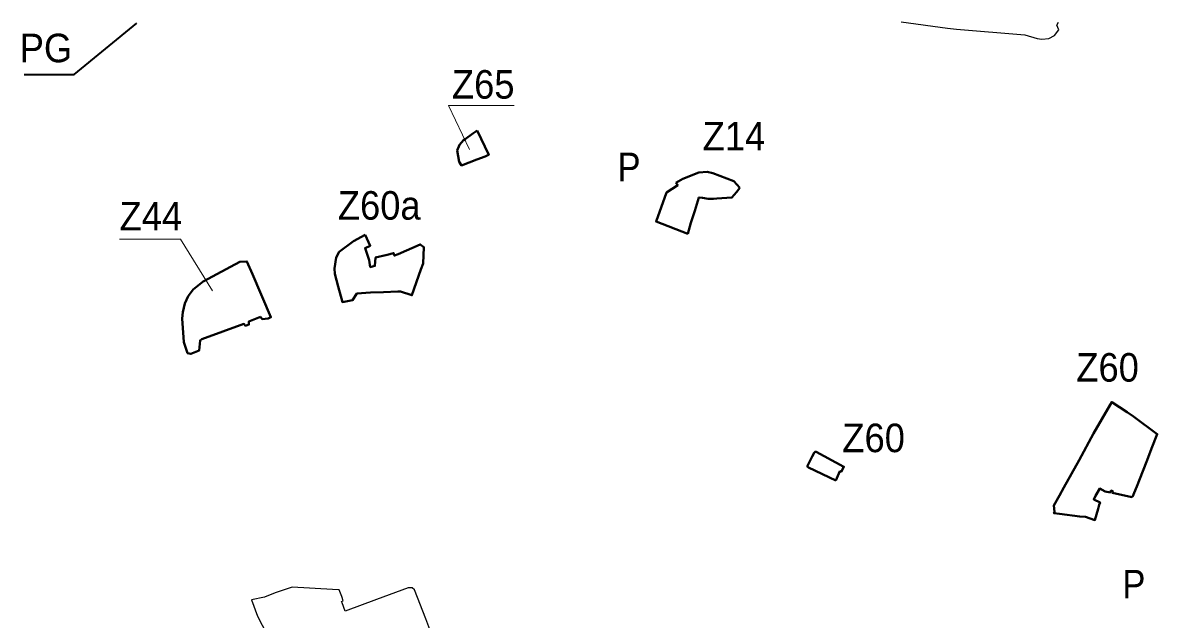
# Model space of a CAD drawing. Extents: x -650276 to -642489, y -1074311 to -1066658.
# Drawn here: x -647715 to -646763, y -1070697 to -1070195 of the extents above; entities that cross this region are included whole.
import ezdxf

# ---------------------------------------------------------------- set-up
doc = ezdxf.new("R2010")
doc.units = 0
doc.header["$LTSCALE"] = 9.6
for name, color, linetype, lineweight in [('42', 7, 'Continuous', 25), ('45', 7, 'Continuous', 40), ('46', 7, 'Continuous', 13), ('60', 7, 'Continuous', 35)]:
    doc.layers.add(name, color=color, linetype=linetype, lineweight=lineweight)

msp = doc.modelspace()

# ---------------------------------------------------------------- linework, layer by layer
at = {"layer": '42'}
for points in [[(-646977.7, -1070194.45), (-646938.98, -1070199.89), (-646931.25, -1070200.56), (-646874.04, -1070205.5), (-646863.66, -1070208.37), (-646859.54, -1070209.09), (-646853.67, -1070208.44), (-646849.15, -1070205.9), (-646845.3, -1070201.3), (-646847.17, -1070197.38), (-646845.76, -1070194.67)], [(-647367.67, -1070720.73), (-647377.04, -1070696.22), (-647386.39, -1070671.74), (-647388.31, -1070669.95), (-647391.74, -1070670.16), (-647418.28, -1070679.89), (-647444.78, -1070689.6), (-647447.31, -1070682.72), (-647447.76, -1070681.5), (-647446.22, -1070680.91), (-647447.58, -1070677.36), (-647449.69, -1070671.81), (-647455.17, -1070671.48), (-647489.21, -1070669.41), (-647496.64, -1070671.93), (-647503.3, -1070674.3), (-647512.51, -1070677.98), (-647523.27, -1070680.11), (-647518.19, -1070693.93), (-647502.59, -1070724.13)]]:
    msp.add_lwpolyline(points, dxfattribs=at)
at = {"layer": '45'}
for points in [[(-647333.87, -1070285.66), (-647324.11, -1070306.21), (-647324.94, -1070306.63), (-647327.18, -1070307.52), (-647333.97, -1070310.22), (-647346.97, -1070315.05), (-647349, -1070312), (-647350.67, -1070302.55), (-647348.677, -1070297.894), (-647345.27, -1070293.99), (-647343.9, -1070292.96), (-647337.56, -1070288.43), (-647334.91, -1070286.51)], [(-647333.87, -1070285.66), (-647324.11, -1070306.21), (-647324.94, -1070306.63), (-647327.18, -1070307.52), (-647333.97, -1070310.22), (-647346.97, -1070315.05), (-647349, -1070312), (-647350.67, -1070302.55), (-647348.677, -1070297.894), (-647345.27, -1070293.99), (-647343.9, -1070292.96), (-647337.56, -1070288.43), (-647334.91, -1070286.51)], [(-647427.8, -1070373.32), (-647437.76, -1070378.66), (-647449.69, -1070387.83), (-647452.17, -1070392.38), (-647453.71, -1070401.81), (-647453.35, -1070406.09), (-647450.51, -1070416.96), (-647446.93, -1070429.99), (-647438.45, -1070428.47), (-647434.85, -1070422.64), (-647423.38, -1070421.87), (-647412.51, -1070421.5), (-647400.41, -1070421.08), (-647398.21, -1070421.15), (-647388.6, -1070424.24), (-647381.11, -1070402.45), (-647379.3, -1070397.57), (-647378.49, -1070383.91), (-647381.65, -1070381.45), (-647400.22, -1070389.64), (-647403.27, -1070390.91), (-647404, -1070388.84), (-647409.36, -1070390.24), (-647419.08, -1070392.52), (-647419.68, -1070399.59), (-647423.58, -1070400.59), (-647424.54, -1070394.78), (-647425.99, -1070390.47), (-647427.96, -1070384.64), (-647423.57, -1070382.64)], [(-647427.8, -1070373.32), (-647437.76, -1070378.66), (-647449.69, -1070387.83), (-647452.17, -1070392.38), (-647453.71, -1070401.81), (-647453.35, -1070406.09), (-647450.51, -1070416.96), (-647446.93, -1070429.99), (-647438.45, -1070428.47), (-647434.85, -1070422.64), (-647423.38, -1070421.87), (-647412.51, -1070421.5), (-647400.41, -1070421.08), (-647398.21, -1070421.15), (-647388.6, -1070424.24), (-647381.11, -1070402.45), (-647379.3, -1070397.57), (-647378.49, -1070383.91), (-647381.65, -1070381.45), (-647400.22, -1070389.64), (-647403.27, -1070390.91), (-647404, -1070388.84), (-647409.36, -1070390.24), (-647419.08, -1070392.52), (-647419.68, -1070399.59), (-647423.58, -1070400.59), (-647424.54, -1070394.78), (-647425.99, -1070390.47), (-647427.96, -1070384.64), (-647423.57, -1070382.64)], [(-647515.73, -1070442.32), (-647514.23, -1070444.18), (-647509.22, -1070443.62), (-647506.95, -1070442.71), (-647522.54, -1070406.51), (-647527.1, -1070395.72), (-647533.1, -1070396.26), (-647564.01, -1070412.59), (-647572.37, -1070419.41), (-647576.48, -1070425.09), (-647579.22, -1070431.05), (-647581.04, -1070438.4), (-647581.54, -1070443.7), (-647580.1, -1070463.69), (-647576.92, -1070473), (-647574.28, -1070473.46), (-647567.32, -1070470.66), (-647566.55, -1070462.22), (-647565.11, -1070461.12), (-647529.74, -1070448.27), (-647528.28, -1070449.87), (-647525.54, -1070448.89), (-647525.45, -1070446.21)], [(-647515.73, -1070442.32), (-647514.23, -1070444.18), (-647509.22, -1070443.62), (-647506.95, -1070442.71), (-647522.54, -1070406.51), (-647527.1, -1070395.72), (-647533.1, -1070396.26), (-647564.01, -1070412.59), (-647572.37, -1070419.41), (-647576.48, -1070425.09), (-647579.22, -1070431.05), (-647581.04, -1070438.4), (-647581.54, -1070443.7), (-647580.1, -1070463.69), (-647576.92, -1070473), (-647574.28, -1070473.46), (-647567.32, -1070470.66), (-647566.55, -1070462.22), (-647565.11, -1070461.12), (-647529.74, -1070448.27), (-647528.28, -1070449.87), (-647525.54, -1070448.89), (-647525.45, -1070446.21)], [(-646802.19, -1070516.26), (-646816.42, -1070540.49), (-646828.45, -1070562.89), (-646841.16, -1070585.79), (-646844.76, -1070592.54), (-646849.72, -1070600.98), (-646848.99, -1070606.28), (-646849.59, -1070607.4), (-646844.96, -1070607.98), (-646827.88, -1070610.12), (-646822.99, -1070610.51), (-646815.05, -1070613.14), (-646812.5, -1070603.78), (-646811.5, -1070600.29), (-646810.82, -1070598.23), (-646816.11, -1070595.8), (-646814.52, -1070592.78), (-646811.06, -1070586.67), (-646806.41, -1070589), (-646802.06, -1070589.93), (-646801.73, -1070588.37), (-646800.13, -1070588.71), (-646800.47, -1070590.28), (-646784.18, -1070593.76), (-646784, -1070593.34), (-646783.59, -1070593.52), (-646779.9, -1070584.92), (-646774.91, -1070571.88), (-646771.17, -1070562.7), (-646767.63, -1070553.09), (-646762.71, -1070540.85), (-646782.63, -1070526.02), (-646788, -1070522.49), (-646800.94, -1070514.04)], [(-646802.19, -1070516.26), (-646816.42, -1070540.49), (-646828.45, -1070562.89), (-646841.16, -1070585.79), (-646844.76, -1070592.54), (-646849.72, -1070600.98), (-646848.99, -1070606.28), (-646849.59, -1070607.4), (-646844.96, -1070607.98), (-646827.88, -1070610.12), (-646822.99, -1070610.51), (-646815.05, -1070613.14), (-646812.5, -1070603.78), (-646811.5, -1070600.29), (-646810.82, -1070598.23), (-646816.11, -1070595.8), (-646814.52, -1070592.78), (-646811.06, -1070586.67), (-646806.41, -1070589), (-646802.06, -1070589.93), (-646801.73, -1070588.37), (-646800.13, -1070588.71), (-646800.47, -1070590.28), (-646784.18, -1070593.76), (-646784, -1070593.34), (-646783.59, -1070593.52), (-646779.9, -1070584.92), (-646774.91, -1070571.88), (-646771.17, -1070562.7), (-646767.63, -1070553.09), (-646762.71, -1070540.85), (-646782.63, -1070526.02), (-646788, -1070522.49), (-646800.94, -1070514.04)], [(-647032.738, -1070579.83), (-647029.168, -1070572.13), (-647028.248, -1070572.63), (-647025.868, -1070568.26), (-647049.248, -1070555.64), (-647050.098, -1070555.74), (-647050.868, -1070556.59), (-647052.498, -1070559.7), (-647056.518, -1070567.41), (-647056.528, -1070568.32), (-647055.518, -1070569.07)]]:
    msp.add_lwpolyline(points, close=True, dxfattribs=at)
for points in [[(-647113.37, -1070333.96), (-647118.28, -1070328.29), (-647135.94, -1070321.54), (-647140.83, -1070320.47), (-647147.66, -1070321.04), (-647161.17, -1070326.29), (-647167.03, -1070329.81)], [(-647167.03, -1070329.81), (-647165.36, -1070331.59), (-647174.81, -1070338.01), (-647183.55, -1070362.35), (-647156.9, -1070372.69)], [(-647156.9, -1070372.69), (-647154.31, -1070363.46), (-647151.09, -1070353.15), (-647147.6, -1070341.95), (-647144.57, -1070342.42), (-647139.84, -1070343.16), (-647135.62, -1070343.32), (-647132.49, -1070342.91)], [(-647132.49, -1070342.91), (-647119.88, -1070342.1), (-647116.03, -1070337.68), (-647113.37, -1070333.96)]]:
    msp.add_lwpolyline(points, dxfattribs=at)
at = {"layer": '46'}
for points in [[(-647302.639, -1070264.673), (-647358.031, -1070264.673), (-647340.193, -1070301.786)], [(-647302.639, -1070264.673), (-647358.031, -1070264.673), (-647340.193, -1070301.786)], [(-647634.056, -1070376.951), (-647582.888, -1070376.951), (-647556.111, -1070420.553)], [(-647634.056, -1070376.951), (-647582.888, -1070376.951), (-647556.111, -1070420.553)]]:
    msp.add_lwpolyline(points, dxfattribs=at)
at = {"layer": '60'}
msp.add_lwpolyline([(-647714.329, -1070238.836), (-647672.08, -1070238.836), (-647619.504, -1070195.616)], dxfattribs=at)
msp.add_lwpolyline([(-647714.329, -1070238.836), (-647672.08, -1070238.836), (-647619.504, -1070195.616)], dxfattribs=at)

# ---------------------------------------------------------------- texts
at = {"layer": '46', "width": 0.95}
for s, p in [('Z65', (-647355.018, -1070259.014)), ('Z65', (-647355.018, -1070259.014)), ('Z14', (-647144.477, -1070302.522)), ('Z60a', (-647450.804, -1070360.702)), ('Z44', (-647634.087, -1070369.724)), ('Z44', (-647634.087, -1070369.724)), ('Z60', (-646830.725, -1070496.795)), ('Z60', (-647027.184, -1070556.06))]:
    msp.add_text(s, height=24, dxfattribs=at).set_placement(p)
at = {"layer": '60'}
for s, width, p in [('PG', 0.95, (-647717.94, -1070228.451)), ('PG', 0.95, (-647717.94, -1070228.451)), ('P', 0.9, (-647215.907, -1070328.431)), ('P', 0.9, (-647215.907, -1070328.431)), ('P', 0.9, (-646791.982, -1070678.937)), ('P', 0.9, (-646791.982, -1070678.937))]:
    msp.add_text(s, height=24, dxfattribs=dict(at, width=width)).set_placement(p)

doc.saveas('drawing.dxf')
